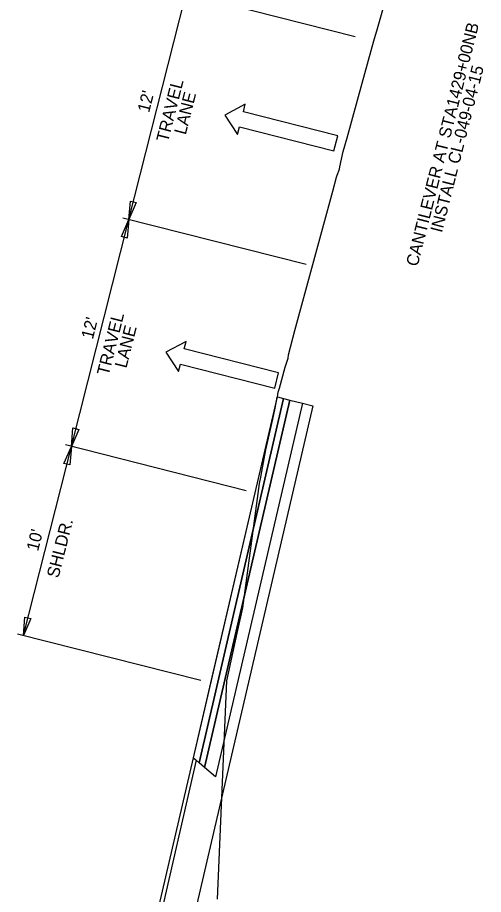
# Model space of a CAD drawing. Extents: x 670003 to 670131, y 737764 to 738002.
# Drawn here: x 670077.64 to 670101.55, y 737845.57 to 737890.53 of the extents above; entities that cross this region are included whole.
import ezdxf

# ---------------------------------------------------------------- set-up
doc = ezdxf.new("R2010")
doc.units = 0
for name, color, linetype in [('R_Alt Surface', 7, 'Continuous'), ('R_Exist Surface', 7, 'Continuous'), ('R_Fin Surface', 7, 'Continuous'), ('R_Horz Alg Annot', 7, 'Continuous'), ('R_MOT', 7, 'Continuous'), ('R_SIGN_ANNOT', 7, 'Continuous')]:
    doc.layers.add(name, color=color, linetype=linetype)

msp = doc.modelspace()

# ---------------------------------------------------------------- linework, layer by layer
at = {"layer": 'R_Alt Surface'}
for points in [[(670091.296, 737871.001), (670091.616, 737870.92), (670087.238, 737852.085), (670086.955, 737852.328)], [(670091.616, 737870.92), (670092.262, 737870.756), (670087.805, 737851.596), (670087.238, 737852.085)]]:
    msp.add_lwpolyline(points, close=True, dxfattribs=at)
msp.add_lwpolyline([(670092.262, 737870.756), (670092.787, 737870.623), (670088.328, 737851.463), (670086.381, 737843.098)], dxfattribs=at)
at = {"layer": 'R_Exist Surface'}
msp.add_lwpolyline([(670087.906, 737845.329), (670088.384, 737856.52), (670088.906, 737858.971), (670089.198, 737860.273), (670089.44, 737862.042), (670090.053, 737866.652), (670090.133, 737866.975), (670090.183, 737867.254), (670090.39, 737868.364), (670090.737, 737869.936), (670090.859, 737870.51), (670090.97, 737871.062), (670090.976, 737871.082), (670091.024, 737871.32), (670091.078, 737871.526), (670091.374, 737872.614), (670091.524, 737873.074), (670091.543, 737873.235), (670091.879, 737874.481), (670093.817, 737881.625), (670094.012, 737882.342), (670094.046, 737882.455), (670094.154, 737882.759), (670094.179, 737882.874), (670094.357, 737883.658), (670094.556, 737884.375), (670095.328, 737887.166), (670095.925, 737889.339), (670096.104, 737889.98), (670097.035, 737893.228)], dxfattribs=at)
at = {"layer": 'R_Fin Surface'}
for points in [[(670082.151, 737835.143), (670083.616, 737840.47), (670080.388, 737841.977), (670080.607, 737842.843), (670080.795, 737842.795), (670084.351, 737842.581), (670086.673, 737852.572), (670087.568, 737856.422), (670089.833, 737866.164), (670090.976, 737871.082)], [(670086.814, 737852.45), (670084.758, 737843.509), (670084.597, 737843.55), (670084.351, 737842.581), (670086.673, 737852.572), (670086.814, 737852.45)]]:
    msp.add_lwpolyline(points, dxfattribs=at)
msp.add_lwpolyline([(670090.976, 737871.082), (670091.296, 737871.001), (670086.955, 737852.328), (670086.673, 737852.572)], close=True, dxfattribs=at)
at = {"layer": 'R_Horz Alg Annot'}
for p, q in [((670083.356, 737880.175), (670086.291, 737891.75)), ((670094.965, 737889.55), (670085.989, 737891.827)), ((670080.406, 737868.543), (670083.356, 737880.175)), ((670092.448, 737877.869), (670083.053, 737880.252)), ((670089.375, 737866.268), (670080.103, 737868.62)), ((670077.947, 737858.85), (670080.406, 737868.543)), ((670087.04, 737856.544), (670077.644, 737858.927))]:
    msp.add_line(p, q, dxfattribs=at)
for points in [[(670083.738, 737881.045), (670083.356, 737880.175), (670083.435, 737881.122)], [(670082.974, 737879.305), (670083.356, 737880.175), (670083.277, 737879.228)], [(670080.788, 737869.414), (670080.406, 737868.543), (670080.485, 737869.49)], [(670080.024, 737867.673), (670080.406, 737868.543), (670080.327, 737867.596)], [(670078.329, 737859.721), (670077.947, 737858.85), (670078.026, 737859.797)]]:
    msp.add_lwpolyline(points, close=True, dxfattribs=at)
at = {"layer": 'R_MOT'}
for p, q in [((670089.328, 737886.093), (670088.281, 737885.533)), ((670089.23, 737885.705), (670089.328, 737886.093)), ((670094.072, 737884.477), (670089.23, 737885.705)), ((670088.281, 737885.533), (670088.935, 737884.542)), ((670088.935, 737884.542), (670089.033, 737884.93)), ((670089.033, 737884.93), (670093.876, 737883.702)), ((670093.876, 737883.702), (670094.072, 737884.477)), ((670086.296, 737873.93), (670085.249, 737873.37)), ((670086.197, 737873.542), (670086.296, 737873.93)), ((670091.04, 737872.314), (670086.197, 737873.542)), ((670085.249, 737873.37), (670085.902, 737872.379)), ((670085.902, 737872.379), (670086.001, 737872.767)), ((670086.001, 737872.767), (670090.843, 737871.539)), ((670090.843, 737871.539), (670091.04, 737872.314))]:
    msp.add_line(p, q, dxfattribs=at)

# ---------------------------------------------------------------- texts
at = {"layer": 'R_Horz Alg Annot'}
for s, p in [("12'", (670084.394, 737885.625)), ("12'", (670081.508, 737874.007)), ("10'", (670078.697, 737863.137))]:
    msp.add_text(s, height=0.63, rotation=75.7686, dxfattribs=at).set_placement(p)
at = {"layer": 'R_SIGN_ANNOT'}
for s, height, p in [('CANTILEVER AT STA1429+00NB', 0.625, (670098.168, 737877.737)), ('INSTALL CL-049-04-15', 0.625, (670099.416, 737879.474)), ('TRAVEL', 0.63, (670085.362, 737884.108)), ('LANE', 0.63, (670086.273, 737884.492)), ('TRAVEL', 0.63, (670082.315, 737872.14)), ('LANE', 0.63, (670083.226, 737872.523)), ('SHLDR.', 0.63, (670079.743, 737861.762))]:
    msp.add_text(s, height=height, rotation=75.7686, dxfattribs=at).set_placement(p)

doc.saveas('drawing.dxf')
